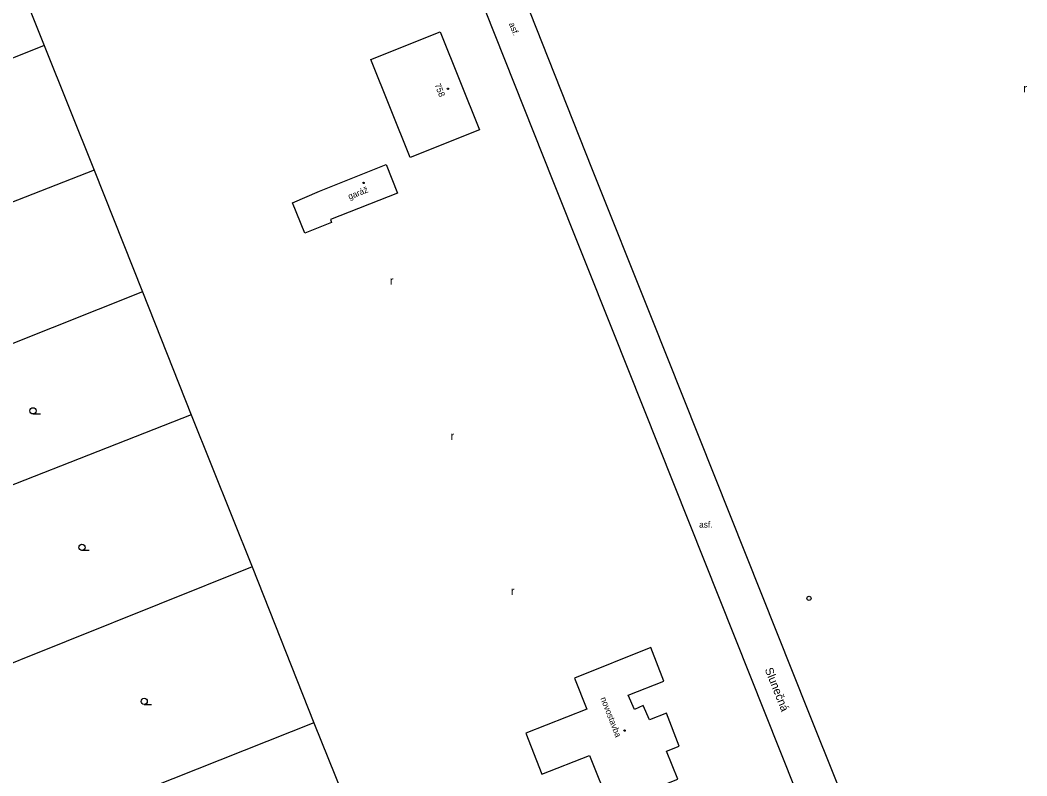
# Model space of a CAD drawing. Extents: x -577457 to -568404, y -1208466 to -1201387.
# Drawn here: x -574991.3 to -574869.6, y -1204595.9 to -1204504.5 of the extents above; entities that cross this region are included whole.
import ezdxf

# ---------------------------------------------------------------- set-up
doc = ezdxf.new("R2010")
doc.units = 0
for name, color, linetype in [('BUDOVY_MĚŘ', 7, 'Continuous'), ('BUDOVY_NEMĚŘ', 7, 'Continuous'), ('NÁZVY_ULIC_TOK_SMĚR', 7, 'Continuous'), ('POMOC_POPIS', 7, 'Continuous'), ('ROZHRANÍ_PLOCH', 7, 'Continuous'), ('ZN_BP', 7, 'Continuous'), ('ZN_BUDOV', 7, 'Continuous'), ('ZN_DOPLŇKOVÉ', 7, 'Continuous'), ('ZN_KULTUR', 7, 'Continuous'), ('Č_POPIS_ORIENT', 7, 'Continuous')]:
    doc.layers.add(name, color=color, linetype=linetype)

msp = doc.modelspace()

# ---------------------------------------------------------------- linework, layer by layer
at = {"layer": 'BUDOVY_MĚŘ'}
for points in [[(-574948.9, -1204509.28), (-574940.55, -1204505.95), (-574935.8, -1204517.78)], [(-574913.5, -1204584.41), (-574915.09, -1204580.35), (-574924.29, -1204584.04), (-574922.79, -1204587.8), (-574930.17, -1204590.7), (-574928.23, -1204595.66), (-574922.5, -1204593.39), (-574920.05, -1204599.52), (-574911.81, -1204596.26), (-574913.19, -1204592.86), (-574911.65, -1204592.25), (-574913.19, -1204588.26), (-574915.23, -1204589.07), (-574915.99, -1204587.34), (-574917.04, -1204587.82), (-574917.83, -1204586.09), (-574913.5, -1204584.41)]]:
    msp.add_lwpolyline(points, dxfattribs=at)
at = {"layer": 'BUDOVY_NEMĚŘ'}
for points in [[(-574935.8, -1204517.78), (-574944.16, -1204521.14), (-574948.9, -1204509.28)], [(-574947.06, -1204522), (-574945.69, -1204525.44), (-574953.79, -1204528.63), (-574953.66, -1204529), (-574956.88, -1204530.29), (-574958.4, -1204526.6), (-574955.12, -1204525.21), (-574947.06, -1204522)]]:
    msp.add_lwpolyline(points, dxfattribs=at)
at = {"layer": 'ROZHRANÍ_PLOCH'}
for points in [[(-574922.21, -1204522.42), (-574934.12, -1204492.26)], [(-574937.43, -1204497.46), (-574926.91, -1204523.95)], [(-574895.96, -1204588.21), (-574915.01, -1204540.45), (-574922.21, -1204522.42)], [(-574926.91, -1204523.95), (-574919.65, -1204542.14), (-574879.21, -1204643.68)], [(-574881.88, -1204623.37), (-574895.96, -1204588.21)]]:
    msp.add_lwpolyline(points, dxfattribs=at)
at = {"layer": 'ZN_BP'}
for radius in [0.25, 0.0005]:
    msp.add_circle((-574895.95, -1204574.4), radius, dxfattribs=at)
at = {"layer": 'ZN_BUDOV'}
for centre in [(-574939.6, -1204512.83), (-574949.8, -1204524.21), (-574918.25, -1204590.38)]:
    msp.add_circle(centre, 0.0875, dxfattribs=at)
at = {"layer": 'ZN_DOPLŇKOVÉ'}
for points in [[(-574994.38, -1204492.75), (-574988.41, -1204507.62)], [(-574988.41, -1204507.62), (-575022.85, -1204521.42)], [(-574988.41, -1204507.62), (-574982.37, -1204522.66)], [(-574982.37, -1204522.66), (-575021.13, -1204537.8)], [(-574982.37, -1204522.66), (-574976.5, -1204537.38)], [(-574976.5, -1204537.38), (-575014.45, -1204552.46)], [(-574976.5, -1204537.38), (-574970.62, -1204552.22)], [(-574970.62, -1204552.22), (-575004.33, -1204565.45)], [(-574970.62, -1204552.22), (-574963.25, -1204570.6)], [(-574963.25, -1204570.6), (-574997.01, -1204584.14)], [(-574963.25, -1204570.6), (-574955.82, -1204589.45)], [(-574955.82, -1204589.45), (-574992.63, -1204604.06)], [(-574955.82, -1204589.45), (-574949.82, -1204604.32)]]:
    msp.add_lwpolyline(points, dxfattribs=at)
at = {"layer": 'ZN_KULTUR'}
for p, q in [((-574989.74, -1204552.12), (-574988.86, -1204552.12)), ((-574983.83, -1204568.6), (-574982.95, -1204568.6)), ((-574976.31, -1204587.23), (-574975.44, -1204587.23))]:
    msp.add_line(p, q, dxfattribs=at)
for centre in [(-574989.74, -1204551.75), (-574983.83, -1204568.23), (-574976.31, -1204586.85)]:
    msp.add_circle(centre, 0.375, dxfattribs=at)

# ---------------------------------------------------------------- texts
at = {"layer": 'NÁZVY_ULIC_TOK_SMĚR'}
msp.add_text('Slunečná', height=1, rotation=291.72, dxfattribs=at).set_placement((-574901.32, -1204583))
at = {"layer": 'POMOC_POPIS'}
for s, rotation, p in [('asf.', 291.67, (-574932.25, -1204504.98)), ('garáž', 21.72, (-574951.5, -1204526.24)), ('novostavba', 291.39, (-574921.18, -1204586.5))]:
    msp.add_text(s, height=0.75, rotation=rotation, dxfattribs=at).set_placement(p)
msp.add_text('asf.', height=0.75, dxfattribs=at).set_placement((-574909.24, -1204565.86))
at = {"layer": 'ZN_KULTUR'}
for p in [(-574870.05, -1204513.26), (-574946.62, -1204536.52), (-574939.27, -1204555.27), (-574931.98, -1204574.02)]:
    msp.add_text('r', height=1, dxfattribs=at).set_placement(p)
at = {"layer": 'Č_POPIS_ORIENT'}
msp.add_text('758', height=0.75, rotation=291.88, dxfattribs=at).set_placement((-574941.23, -1204512.35))

doc.saveas('drawing.dxf')
